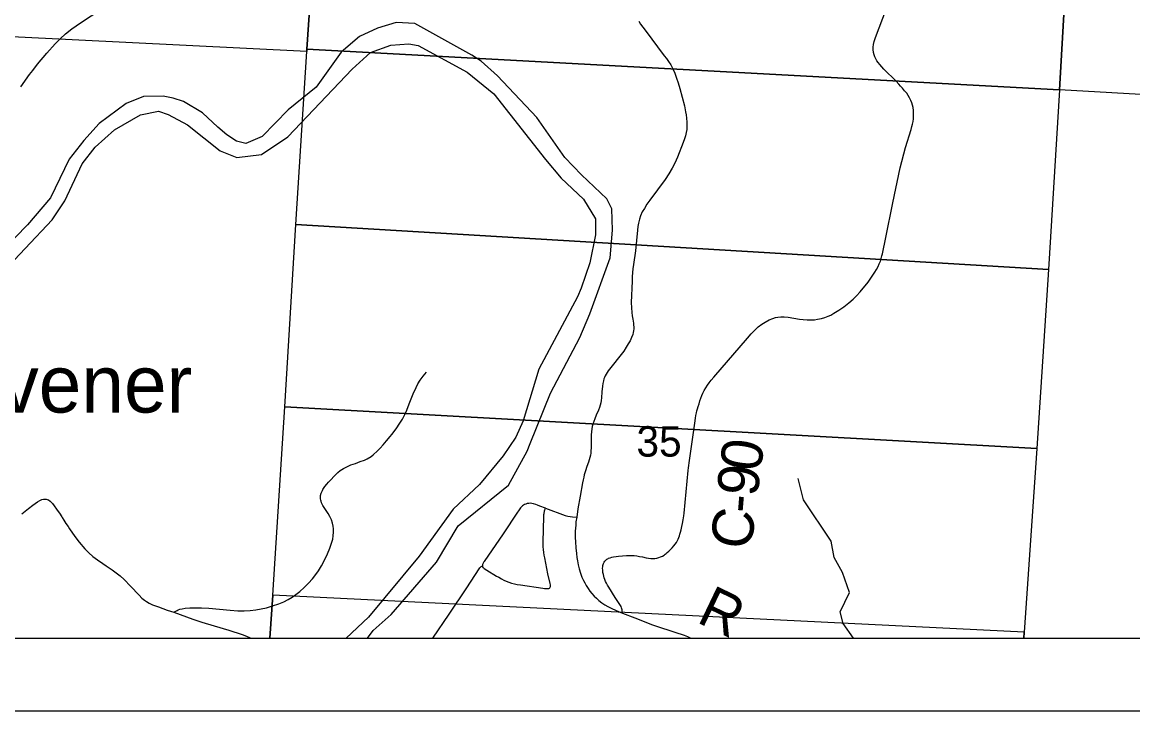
# Model space of a CAD drawing. Extents: x 0 to 34, y 0 to 22.
# Drawn here: x 5.548 to 7.078, y 14 to 14.948 of the extents above; entities that cross this region are included whole.
import ezdxf

# ---------------------------------------------------------------- set-up
doc = ezdxf.new("R2010")
doc.units = 0
for name, color, linetype in [('Default', 7, 'Continuous'), ('GM_X_County_Road', 7, 'Continuous'), ('GM_X_County_Road_Text', 7, 'Continuous'), ('GM_X_Major_River', 7, 'Continuous'), ('GM_X_Minor_River', 7, 'Continuous'), ('GM_X_Section', 7, 'Continuous'), ('GM_X_Section_Text', 7, 'Continuous'), ('GM_X_State_Route', 7, 'Continuous'), ('GM_X_Township_Road', 7, 'Continuous'), ('GM_X_Unincorporated_Text', 7, 'Continuous'), ('SH_Data', 7, 'Continuous'), ('SH_Text', 7, 'Continuous')]:
    doc.layers.add(name, color=color, linetype=linetype)

msp = doc.modelspace()

# ---------------------------------------------------------------- linework, layer by layer
at = {"layer": 'Default'}
msp.add_lwpolyline([(4.9458, 15.9099), (4.8987, 15.3279), (4.8734, 15.0246), (4.8164, 14.1), (8.0885, 14.1)], dxfattribs=at)
for points in [[(4.8257, 14.1), (5.8897, 14.1), (5.8935, 14.1589), (5.91, 14.4183), (5.9253, 14.6691), (5.9405, 14.9074), (4.8777, 14.9601)], [(6.9283, 14.1), (7.9595, 14.1), (8.0002, 14.6926), (8.0084, 14.7203), (8.0044, 14.7771), (8.0042, 14.7772), (7.9714, 14.8008), (7.21, 14.8415), (6.9776, 14.8549), (6.9622, 14.6076), (6.946, 14.3611), (6.9289, 14.1084)], [(5.8897, 14.1), (6.9283, 14.1), (6.9289, 14.1084), (5.8935, 14.1589)]]:
    msp.add_lwpolyline(points, close=True, dxfattribs=at)
at = {"layer": 'GM_X_County_Road'}
for points in [[(6.3978, 14.9492), (6.4003, 14.9453), (6.4065, 14.9367), (6.433, 14.9016), (6.436, 14.8976), (6.4388, 14.8937), (6.4418, 14.8889), (6.4444, 14.8843), (6.4474, 14.8777), (6.45, 14.8709), (6.4522, 14.8644), (6.4545, 14.8567), (6.4606, 14.8328), (6.4624, 14.8243), (6.4631, 14.8201), (6.4637, 14.8159), (6.4642, 14.8102), (6.4642, 14.8052), (6.4638, 14.8002), (6.4631, 14.7958), (6.462, 14.7913), (6.4608, 14.7872), (6.4591, 14.7822), (6.4512, 14.7621), (6.4474, 14.7538), (6.444, 14.747), (6.4393, 14.7389), (6.4343, 14.7312), (6.413, 14.703), (6.4089, 14.6971), (6.4055, 14.6915), (6.4027, 14.6867), (6.4003, 14.6813), (6.3987, 14.6765), (6.3974, 14.671), (6.3966, 14.6665), (6.3959, 14.6617), (6.3931, 14.633), (6.3904, 14.6144), (6.3897, 14.6082), (6.3892, 14.6033), (6.3888, 14.5973), (6.3885, 14.5912), (6.3875, 14.5619), (6.3876, 14.5545), (6.3881, 14.5483), (6.3887, 14.5438), (6.3895, 14.5392), (6.3904, 14.5335), (6.3907, 14.5307), (6.3908, 14.5283), (6.3908, 14.5258), (6.3906, 14.5231), (6.3902, 14.5207), (6.3896, 14.5181), (6.3879, 14.514), (6.3858, 14.5094), (6.3833, 14.5049), (6.3805, 14.5003), (6.377, 14.4952), (6.3557, 14.4678), (6.3528, 14.4632), (6.3515, 14.4609), (6.3505, 14.4588), (6.3497, 14.4567), (6.349, 14.4543), (6.3483, 14.4507), (6.3478, 14.4468), (6.3471, 14.439), (6.3464, 14.4308), (6.346, 14.4271), (6.3454, 14.4238), (6.3447, 14.4206), (6.3437, 14.4174), (6.3423, 14.4139), (6.3392, 14.4069), (6.3371, 14.4017), (6.3357, 14.3981), (6.3346, 14.3947), (6.3336, 14.3913), (6.333, 14.3881), (6.3326, 14.3841), (6.3324, 14.38), (6.3322, 14.371), (6.3321, 14.362), (6.3319, 14.3578), (6.3316, 14.3546), (6.3311, 14.3518), (6.3305, 14.3487), (6.3296, 14.3454), (6.3285, 14.3421), (6.3264, 14.3363), (6.3244, 14.3304), (6.3235, 14.3277), (6.3226, 14.3248), (6.3219, 14.3216), (6.3211, 14.318), (6.3204, 14.3139), (6.317, 14.2955), (6.314, 14.2779), (6.3123, 14.2665), (6.3113, 14.2599), (6.3109, 14.2556), (6.3105, 14.2513), (6.3103, 14.2473), (6.3103, 14.2431), (6.3104, 14.2384), (6.3107, 14.2326), (6.3112, 14.2241), (6.3119, 14.2164), (6.3126, 14.2108), (6.3133, 14.2062), (6.3143, 14.201), (6.3156, 14.1952), (6.3173, 14.1895), (6.3195, 14.1839), (6.3216, 14.1795), (6.3235, 14.1759), (6.3253, 14.1725), (6.3279, 14.1684), (6.3305, 14.1647), (6.3331, 14.1616), (6.3364, 14.1578), (6.3394, 14.155), (6.3429, 14.1519), (6.347, 14.1485), (6.3511, 14.1458), (6.3554, 14.1434), (6.3599, 14.1413), (6.3667, 14.1382), (6.3754, 14.1345), (6.3923, 14.1279), (6.4169, 14.1182), (6.4515, 14.1068), (6.456, 14.1054), (6.4602, 14.1039), (6.4648, 14.1021), (6.4697, 14.1)], [(6.3754, 14.1345), (6.3747, 14.1388), (6.3744, 14.1404), (6.3741, 14.1417), (6.3735, 14.1433), (6.3728, 14.1449), (6.3719, 14.1463), (6.3653, 14.1559), (6.3565, 14.1701), (6.3546, 14.1731), (6.3533, 14.1757), (6.3521, 14.1781), (6.3511, 14.1806), (6.3503, 14.1829), (6.3496, 14.1853), (6.349, 14.1877), (6.3485, 14.1903), (6.3482, 14.1934), (6.348, 14.1963), (6.3481, 14.1982), (6.3483, 14.2), (6.3486, 14.2013), (6.3491, 14.2028), (6.35, 14.2044), (6.351, 14.2058), (6.3523, 14.2073), (6.3538, 14.2085), (6.355, 14.2092), (6.3562, 14.2099), (6.3582, 14.2106), (6.3605, 14.2114), (6.363, 14.2119), (6.3665, 14.2124), (6.37, 14.2127), (6.3811, 14.2136), (6.3851, 14.2138), (6.3882, 14.2138), (6.3915, 14.2136), (6.3951, 14.2132), (6.399, 14.2125), (6.4031, 14.2117), (6.4081, 14.2107), (6.4113, 14.2101), (6.4144, 14.2096), (6.4174, 14.2094), (6.4199, 14.2096), (6.4228, 14.21), (6.4253, 14.2108), (6.4276, 14.2117), (6.4303, 14.213), (6.4326, 14.2144), (6.4342, 14.2156), (6.4357, 14.2167), (6.4371, 14.2179), (6.4392, 14.2197), (6.4412, 14.2217), (6.444, 14.2245), (6.4462, 14.227), (6.4479, 14.2292), (6.4496, 14.2318), (6.451, 14.2342), (6.452, 14.2363), (6.453, 14.2387), (6.4537, 14.2406), (6.4544, 14.2429), (6.4553, 14.2457), (6.4562, 14.2491), (6.4572, 14.2535), (6.4581, 14.2576), (6.459, 14.2627), (6.4594, 14.2654), (6.4598, 14.2685), (6.4602, 14.2719), (6.4659, 14.3309), (6.4663, 14.3345), (6.4666, 14.3377), (6.4672, 14.3415), (6.4749, 14.3957), (6.476, 14.4026), (6.4766, 14.4066), (6.4773, 14.41), (6.4779, 14.4127), (6.4787, 14.4157), (6.4796, 14.4187), (6.4808, 14.4226), (6.4821, 14.4265), (6.4835, 14.4303), (6.4848, 14.4339), (6.4861, 14.4371), (6.4879, 14.4407), (6.4902, 14.4446), (6.4924, 14.4482), (6.4947, 14.4516), (6.4976, 14.4552), (6.5011, 14.4594), (6.5474, 14.513), (6.5525, 14.5188), (6.5575, 14.5238), (6.5625, 14.5283), (6.5674, 14.5321), (6.572, 14.5351), (6.5774, 14.5379), (6.5825, 14.5401), (6.586, 14.5412), (6.5895, 14.542), (6.5937, 14.5424), (6.598, 14.5424), (6.6034, 14.5418), (6.619, 14.5392), (6.6244, 14.5386), (6.63, 14.5382), (6.6348, 14.5381), (6.6397, 14.5383), (6.6441, 14.5389), (6.6495, 14.5399), (6.6543, 14.5414), (6.6588, 14.5431), (6.6622, 14.5446), (6.6666, 14.5471), (6.6734, 14.5513), (6.6801, 14.5559), (6.6874, 14.5616), (6.693, 14.5665), (6.6978, 14.5712), (6.7027, 14.5768), (6.7136, 14.5901), (6.7204, 14.5997), (6.7229, 14.6035), (6.7252, 14.6076), (6.7274, 14.6115), (6.7291, 14.6151), (6.7306, 14.6187), (6.7318, 14.6224), (6.7328, 14.626), (6.7335, 14.6288), (6.7381, 14.6516), (6.7476, 14.699), (6.7581, 14.7474), (6.7654, 14.7755), (6.7729, 14.8), (6.7741, 14.8041), (6.775, 14.8076), (6.7756, 14.8113), (6.7761, 14.815), (6.7763, 14.8185), (6.7764, 14.8223), (6.7762, 14.8263), (6.7756, 14.8302), (6.7748, 14.8337), (6.7738, 14.8366), (6.7725, 14.8401), (6.7709, 14.8436), (6.769, 14.8469), (6.7669, 14.8499), (6.7641, 14.8535), (6.7612, 14.8569), (6.7585, 14.8598), (6.756, 14.8625), (6.7523, 14.8664), (6.7356, 14.8832), (6.7326, 14.8865), (6.7299, 14.8895), (6.7277, 14.8923), (6.7259, 14.8948), (6.7245, 14.8972), (6.7231, 14.9001), (6.7221, 14.9028), (6.7213, 14.9061), (6.7209, 14.91), (6.7209, 14.9132), (6.7213, 14.917), (6.7223, 14.9213), (6.7235, 14.9255), (6.7253, 14.9304), (6.7375, 14.9629)], [(5.548, 14.2709), (5.557, 14.2784), (5.5628, 14.283), (5.5695, 14.2876), (5.5727, 14.2895), (5.5755, 14.2908), (5.5779, 14.2913), (5.5797, 14.2914), (5.5816, 14.2912), (5.5827, 14.2909), (5.5844, 14.2902), (5.587, 14.2884), (5.5899, 14.2853), (5.598, 14.2745), (5.5998, 14.2719), (5.6029, 14.267)], [(5.6029, 14.267), (5.6034, 14.2662), (5.6057, 14.2625), (5.6086, 14.2578), (5.6115, 14.2537), (5.6135, 14.2506), (5.6209, 14.2399), (5.627, 14.232), (5.6347, 14.2231), (5.6403, 14.2173), (5.6459, 14.2124), (5.6519, 14.2079), (5.6595, 14.2026), (5.6642, 14.1996), (5.6725, 14.1941), (5.678, 14.19), (5.6832, 14.1856), (5.6887, 14.1806), (5.6978, 14.1715), (5.7095, 14.1589), (5.7134, 14.155), (5.7167, 14.1523), (5.7198, 14.1502), (5.7235, 14.1481), (5.728, 14.146), (5.7361, 14.1429), (5.7483, 14.1384), (5.7574, 14.1358), (5.7745, 14.1294), (5.7833, 14.1262), (5.7957, 14.1221), (5.8129, 14.1168), (5.8332, 14.111), (5.8515, 14.105), (5.8573, 14.1029), (5.8624, 14.1005), (5.8632, 14.1)]]:
    msp.add_lwpolyline(points, dxfattribs=at)
at = {"layer": 'GM_X_Major_River'}
for points in [[(6.0241, 14.1), (6.032, 14.1105), (6.0568, 14.1326), (6.1192, 14.2047), (6.1492, 14.2546), (6.2185, 14.3104), (6.2439, 14.3572), (6.2484, 14.3678), (6.276, 14.437), (6.3164, 14.5139), (6.3303, 14.5462), (6.3582, 14.6234), (6.3618, 14.6614), (6.3605, 14.6909), (6.3536, 14.7046), (6.319, 14.7377), (6.2958, 14.7615), (6.2573, 14.8167), (6.2033, 14.874), (6.1809, 14.894), (6.168, 14.9023), (6.0891, 14.9462), (6.0637, 14.9476), (6.0377, 14.9398), (6.0131, 14.9279), (5.9879, 14.9065), (5.9534, 14.8585), (5.915, 14.8272), (5.8789, 14.7905), (5.8566, 14.7809), (5.8437, 14.7839), (5.8304, 14.7929), (5.8179, 14.8031), (5.7966, 14.8231), (5.7704, 14.8385), (5.7564, 14.8433), (5.7428, 14.8459), (5.7156, 14.8454), (5.6918, 14.8357), (5.6545, 14.8082), (5.6335, 14.7849), (5.6132, 14.7594), (5.5874, 14.7061), (5.5558, 14.6688), (5.4896, 14.6012)], [(5.5146, 14.5968), (5.5898, 14.6758), (5.6071, 14.7017), (5.631, 14.7527), (5.649, 14.7759), (5.6757, 14.7996), (5.7115, 14.8203), (5.7361, 14.8254), (5.7494, 14.8209), (5.7759, 14.8063), (5.8211, 14.7709), (5.8439, 14.7615), (5.8779, 14.7659), (5.9144, 14.79), (6.0028, 14.8831), (6.0284, 14.906), (6.0563, 14.916), (6.0809, 14.9181), (6.0938, 14.9155), (6.1613, 14.8791), (6.1981, 14.8493), (6.2693, 14.7587), (6.2907, 14.733), (6.3215, 14.704), (6.3382, 14.6772), (6.338, 14.6552), (6.3306, 14.6164), (6.3183, 14.5818), (6.3135, 14.5697), (6.2603, 14.4703), (6.2384, 14.3989), (6.2283, 14.3764), (6.2111, 14.3509), (6.1784, 14.3116), (6.1422, 14.2777), (6.0953, 14.2129), (6.0254, 14.129), (5.9945, 14.1)]]:
    msp.add_lwpolyline(points, dxfattribs=at)
at = {"layer": 'GM_X_Minor_River'}
msp.add_lwpolyline([(6.6937, 14.1), (6.6792, 14.1202), (6.6751, 14.1362), (6.688, 14.1628), (6.6783, 14.1901), (6.6672, 14.2109), (6.663, 14.2335), (6.6246, 14.2905), (6.6172, 14.3196)], dxfattribs=at)
at = {"layer": 'GM_X_Section'}
for points in [[(4.9568, 15.9843), (6.0049, 15.9328), (5.9932, 15.6936), (5.9754, 15.4391), (5.9587, 15.1787), (5.9407, 14.9107), (5.9405, 14.9074), (4.8777, 14.9601)], [(7.0366, 15.8787), (7.2798, 15.8662), (7.258, 15.5464), (7.2406, 15.29), (7.2246, 15.0549), (7.21, 14.8415), (6.9776, 14.8549), (6.9928, 15.1186), (7.0075, 15.3738), (7.0224, 15.6312)], [(6.9928, 15.1186), (6.9776, 14.8549), (5.9407, 14.9107), (5.9587, 15.1787)], [(5.9407, 14.9107), (6.9776, 14.8549), (6.9622, 14.6076), (5.9253, 14.6691), (5.9405, 14.9074)], [(6.9622, 14.6076), (6.946, 14.3611), (5.91, 14.4183), (5.9253, 14.6691)], [(5.91, 14.4183), (6.946, 14.3611), (6.9289, 14.1084), (5.8935, 14.1589)]]:
    msp.add_lwpolyline(points, close=True, dxfattribs=at)
at = {"layer": 'GM_X_State_Route'}
msp.add_lwpolyline([(5.5467, 14.859), (5.5586, 14.8757), (5.5628, 14.8814), (5.5696, 14.8899), (5.5825, 14.905), (5.594, 14.9179), (5.6008, 14.9251), (5.608, 14.9319), (5.6166, 14.9386), (5.6289, 14.9471), (5.658, 14.9663)], dxfattribs=at)
at = {"layer": 'GM_X_Township_Road'}
for points in [[(5.7574, 14.1358), (5.7618, 14.1378), (5.7634, 14.1388), (5.7657, 14.1397), (5.7687, 14.1405), (5.773, 14.1411), (5.7792, 14.1415), (5.786, 14.1417), (5.7954, 14.1415), (5.8053, 14.141), (5.835, 14.1383), (5.8455, 14.1376), (5.8542, 14.1375), (5.8623, 14.138), (5.8703, 14.1389), (5.8776, 14.1401), (5.8849, 14.1419), (5.8932, 14.1443), (5.9021, 14.1473), (5.9089, 14.1501), (5.915, 14.1532), (5.9203, 14.1564), (5.9254, 14.16), (5.9308, 14.1643), (5.9368, 14.1696), (5.9429, 14.1758), (5.9483, 14.1818), (5.953, 14.1876), (5.9565, 14.1927), (5.9608, 14.1996), (5.9649, 14.2072), (5.9691, 14.2162), (5.9722, 14.2237), (5.9747, 14.2308), (5.9761, 14.2361), (5.977, 14.241), (5.9774, 14.246), (5.9773, 14.2503), (5.9769, 14.254), (5.9759, 14.2583), (5.9743, 14.2629), (5.9722, 14.2674), (5.9697, 14.2717), (5.9652, 14.2784), (5.9626, 14.2827), (5.9609, 14.286), (5.9602, 14.2884), (5.9597, 14.2901), (5.9595, 14.2918), (5.9593, 14.2931), (5.9593, 14.2945), (5.9595, 14.2963), (5.9602, 14.2993), (5.9611, 14.3015), (5.9619, 14.3034), (5.9625, 14.3044), (5.9653, 14.3086), (5.968, 14.3119), (5.9704, 14.3147), (5.9729, 14.3174), (5.9784, 14.3232), (5.9833, 14.3278), (5.9866, 14.3305), (5.9912, 14.3335), (5.9955, 14.3358), (6.0012, 14.3383), (6.0076, 14.3405), (6.014, 14.3429), (6.0198, 14.3451), (6.0237, 14.347), (6.029, 14.3501), (6.032, 14.3524), (6.0329, 14.3531), (6.037, 14.3569), (6.0414, 14.3614), (6.0455, 14.366), (6.0503, 14.3716), (6.0551, 14.3774), (6.0574, 14.3802), (6.0634, 14.3881), (6.0687, 14.3957), (6.0723, 14.4015), (6.0755, 14.4076), (6.0783, 14.4138), (6.0817, 14.4224), (6.0871, 14.4363), (6.0909, 14.4448), (6.0934, 14.4498), (6.0966, 14.4551), (6.1006, 14.4606), (6.1053, 14.4661)], [(6.2694, 14.2787), (6.2616, 14.2818), (6.2584, 14.283), (6.2558, 14.284), (6.2529, 14.2848), (6.2504, 14.2853), (6.248, 14.2856), (6.2462, 14.2855), (6.2442, 14.2852), (6.2423, 14.2846), (6.2406, 14.2838), (6.2391, 14.283), (6.2377, 14.2819), (6.2363, 14.2807), (6.235, 14.2793), (6.2338, 14.2778), (6.2319, 14.2753), (6.2307, 14.2735), (6.211, 14.2434), (6.1849, 14.2056), (6.1843, 14.2048), (6.1839, 14.2041), (6.1834, 14.2031), (6.1829, 14.2021), (6.1826, 14.2014), (6.1824, 14.2007), (6.1823, 14.1997)], [(6.2683, 14.2104), (6.2676, 14.2143), (6.267, 14.218), (6.2666, 14.2222), (6.2663, 14.2255), (6.2661, 14.2286), (6.2662, 14.2326), (6.267, 14.2669), (6.267, 14.2686), (6.2671, 14.2702), (6.2673, 14.2715), (6.2675, 14.2728), (6.2677, 14.2739), (6.2681, 14.2752), (6.2694, 14.2787), (6.2965, 14.2689), (6.3003, 14.2678), (6.3035, 14.2673), (6.3065, 14.267), (6.3123, 14.2665)], [(6.1143, 14.1), (6.1368, 14.1331), (6.1608, 14.1691), (6.1781, 14.1953), (6.1789, 14.1967), (6.1798, 14.1977), (6.1808, 14.1986), (6.1823, 14.1997)], [(6.1823, 14.1997), (6.1824, 14.1984), (6.1829, 14.1974), (6.1838, 14.1966), (6.1849, 14.1958), (6.1884, 14.1936), (6.202, 14.1853), (6.205, 14.1837), (6.2086, 14.1818), (6.2121, 14.1799), (6.2153, 14.1785), (6.2187, 14.1771), (6.2223, 14.1758), (6.2264, 14.1747), (6.2301, 14.174), (6.2347, 14.1732), (6.2657, 14.1686), (6.2679, 14.1683), (6.2702, 14.1681), (6.2713, 14.1681), (6.2725, 14.1682), (6.2738, 14.1685), (6.2746, 14.1689), (6.2752, 14.1694), (6.2758, 14.1702), (6.2761, 14.1712), (6.2761, 14.1722)], [(6.2761, 14.1722), (6.276, 14.1733), (6.2756, 14.1754), (6.2723, 14.1887), (6.2683, 14.2104)]]:
    msp.add_lwpolyline(points, dxfattribs=at)
at = {"layer": 'SH_Data'}
for p, q in [((2.1, 14.1), (8.9, 14.1)), ((2, 14), (9, 14))]:
    msp.add_line(p, q, dxfattribs=at)
at = {"layer": 'SH_Text'}
msp.add_lwpolyline([(2.1, 14.1), (8.0885, 14.1)], dxfattribs=at)

# ---------------------------------------------------------------- texts
at = {"layer": 'GM_X_County_Road_Text'}
for s, rotation, p in [('0', 81.9542, (6.5653, 14.3279)), ('9', 83.35, (6.5613, 14.2935)), ('-', 85.3252, (6.5594, 14.2708)), ('C', 80.4007, (6.551, 14.2195)), ('R', 334.3985, (6.4759, 14.1226))]:
    msp.add_text(s, height=0.0568, rotation=rotation, dxfattribs=at).set_placement(p)
at = {"layer": 'GM_X_Section_Text'}
msp.add_text('35', height=0.04186, rotation=0, dxfattribs=at).set_placement((6.3946, 14.3498))
at = {"layer": 'GM_X_Unincorporated_Text'}
msp.add_text('Thivener', height=0.07898, rotation=0, dxfattribs=at).set_placement((5.3716, 14.4105))

doc.saveas('drawing.dxf')
